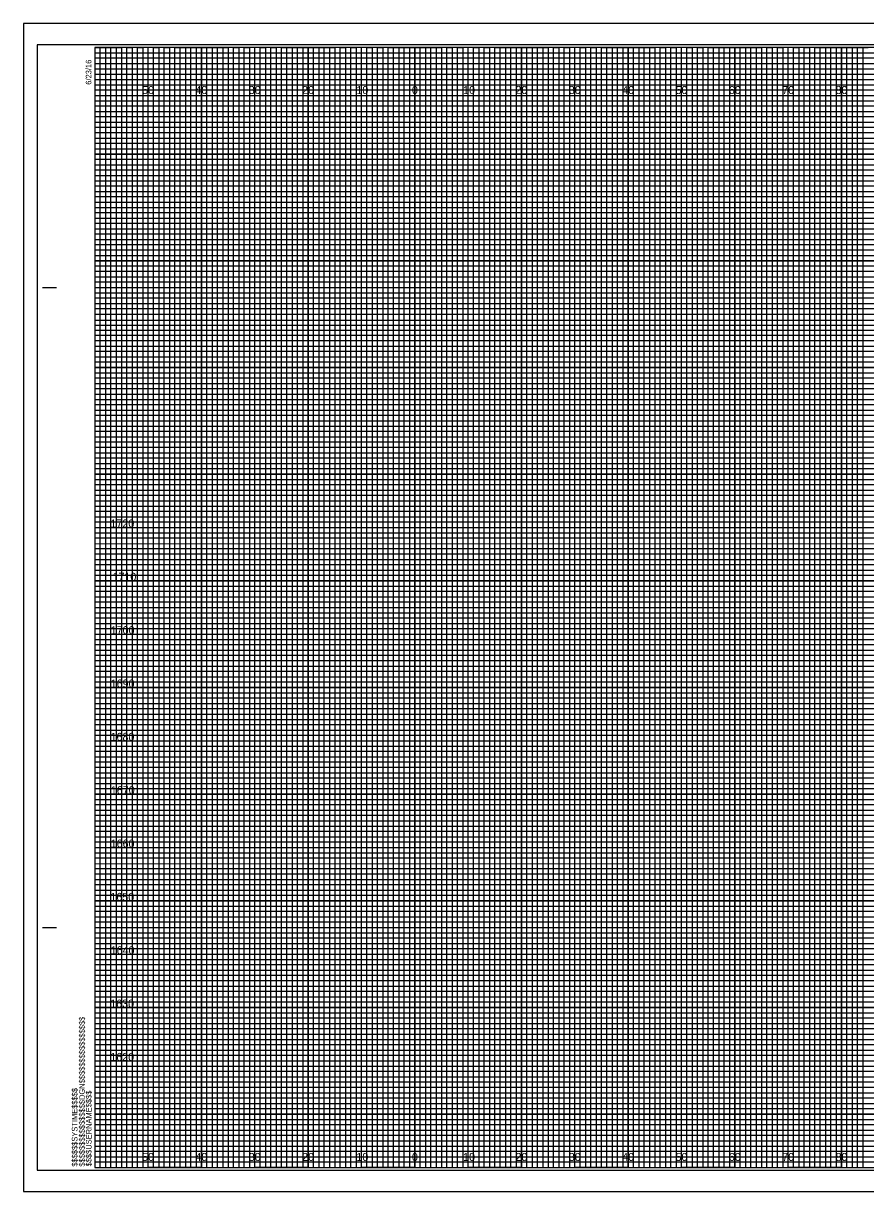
# Model space of a CAD drawing. Extents: x -13 to 323, y -5 to 6154.
# Drawn here: x -13.4 to 144.5, y 3295.5 to 3514.5 of the extents above; entities that cross this region are included whole.
import ezdxf

# ---------------------------------------------------------------- set-up
doc = ezdxf.new("R2010")
doc.units = 0
for name, color, linetype in [('Prop Retaining Wall', 7, 'Continuous'), ('Prop XS Alignment Label', 7, 'Continuous'), ('Prop XS DDE', 7, 'Continuous'), ('Prop XS DDE Elevations', 7, 'Continuous'), ('Prop XS DDE Slope Text', 7, 'Continuous'), ('Prop XS Earthwork Shape', 7, 'Continuous'), ('Prop XS Elevation Labels', 7, 'Continuous'), ('Prop XS Station Labels', 7, 'Continuous'), ('Raster_Level_0', 7, 'Continuous'), ('Scratch_Level_3', 7, 'Continuous'), ('Sheet Cutting Line CELL', 7, 'Continuous')]:
    doc.layers.add(name, color=color, linetype=linetype)

msp = doc.modelspace()

# ---------------------------------------------------------------- linework, layer by layer
at = {"layer": 'Prop Retaining Wall'}
for p, q in [((0, 3509), (260, 3509)), ((260, 3507.98), (0, 3507.98)), ((0, 3507.98), (0, 3507)), ((0, 3507), (260, 3507)), ((260, 3505.89), (0, 3505.89)), ((0, 3505.89), (0, 3504)), ((0, 3504), (320, 3504))]:
    msp.add_line(p, q, dxfattribs=at)
for points in [[(0, 3503), (270, 3503), (320, 3503), (320, 3502), (0, 3502)], [(0, 3501), (320, 3501), (320, 3499), (0, 3499)], [(0, 3498), (320, 3498), (320, 3497), (0, 3496.98)], [(0, 3496), (320, 3496), (320, 3494), (0, 3494)], [(0, 3493), (320, 3493), (320, 3492), (0, 3492)], [(0, 3491), (320, 3491), (320, 3489), (0, 3489)], [(0, 3488), (320, 3488), (320, 3487), (0, 3487)], [(0, 3486), (320, 3486), (320, 3484), (0, 3484)], [(0, 3483), (320, 3483), (320, 3482), (0, 3482)], [(0, 3481), (320, 3481), (320, 3479), (0, 3479)], [(0, 3478), (320, 3478), (320, 3477), (0, 3477)], [(0, 3476), (320, 3476), (320, 3473.95), (320, 3473), (320, 3472), (0, 3472)], [(0, 3474), (320, 3474), (320, 3473), (0, 3473)], [(0, 3471), (320, 3471), (320, 3469), (0, 3469.03)], [(0, 3469.03), (320, 3469), (320, 3468), (0, 3468)], [(0, 3467), (320, 3467), (320, 3466), (0, 3466)], [(0, 3464), (320, 3464), (320, 3463), (0, 3463)], [(0, 3462), (320, 3462), (320, 3461), (0, 3461)], [(-0.07, 3458.89), (320, 3458.89), (320, 3457.88), (-0.07, 3457.88)], [(0, 3457), (320, 3457), (320, 3456), (0, 3456)], [(0, 3454), (320, 3454), (320, 3453), (0, 3453)], [(0, 3452), (320, 3452), (320, 3451), (0, 3451)], [(0, 3449), (320, 3449), (320, 3448), (0, 3448)], [(0, 3447), (320, 3447), (320, 3446), (0, 3446)], [(0, 3444), (320, 3444), (320, 3443), (0, 3443)], [(0, 3442), (320, 3442), (320, 3441), (0, 3441)], [(0, 3439), (320, 3439), (319.99, 3437.98), (0, 3438)], [(0, 3437), (320, 3437), (320, 3436), (0, 3436)], [(0, 3434), (320, 3434), (320, 3433), (0, 3433)], [(0, 3432), (320, 3432), (320, 3431), (0, 3431)], [(0, 3429), (320, 3429), (320, 3428), (0, 3428)], [(0, 3427), (320, 3427), (320, 3426), (0, 3426)], [(0, 3424), (320, 3424), (320, 3423), (0, 3423)], [(0, 3422), (320, 3422), (320, 3421), (0, 3421)], [(0, 3419), (320, 3419), (320, 3418), (0, 3418)], [(0, 3416.99), (320.07, 3416.91), (320, 3416), (0, 3416)], [(0, 3414), (320, 3414), (320, 3413), (0, 3413)], [(0, 3412), (320, 3412), (320, 3411), (0, 3411)], [(0, 3409), (320, 3409), (320, 3408), (0, 3408)], [(0, 3407), (320, 3407), (320, 3406), (0, 3406)], [(0, 3404), (320, 3404), (320, 3403), (0, 3403)], [(0, 3402), (320, 3402), (320, 3401), (0, 3401)], [(0, 3399), (320, 3399), (320, 3398), (0, 3398)], [(0, 3397), (320, 3397), (320, 3396), (0, 3396)], [(0, 3394), (320, 3394), (320, 3393), (0, 3393)], [(0, 3392), (320, 3392), (320, 3391), (0, 3391)], [(0, 3389), (320, 3389), (320, 3388), (0, 3388)], [(0, 3387), (320, 3387), (320, 3386), (0, 3386)], [(0, 3384), (320, 3384), (320, 3383), (0, 3383)], [(0, 3382), (320, 3382), (320, 3381), (0, 3381)], [(0, 3379), (320, 3379), (319.99, 3377.98), (0, 3378)], [(0, 3377), (320, 3377), (320, 3376), (0, 3376)], [(0, 3374), (320, 3374), (320, 3373), (0, 3373)], [(0, 3372), (320, 3372), (320, 3371), (0, 3371)], [(0, 3369), (320, 3369), (320, 3368), (0, 3368)], [(0, 3367), (320, 3367), (320, 3366), (0, 3366)], [(0, 3364), (320, 3364), (320, 3363), (0, 3363)], [(0, 3362), (320, 3362), (320, 3361), (0, 3361)], [(0, 3359), (320, 3359), (320, 3358), (0, 3358)], [(0, 3356.99), (320.07, 3356.91), (320, 3356), (0, 3356)], [(0, 3354), (320, 3354), (320, 3353), (0, 3353)], [(0, 3352), (320, 3352), (320, 3351), (0, 3351)], [(0, 3349), (320, 3349), (320, 3348), (0, 3348)], [(0, 3347), (320, 3347), (320, 3346), (0, 3346)], [(0, 3344), (320, 3344), (320, 3343), (0, 3343)], [(0, 3342), (320, 3342), (320, 3341), (0, 3341)], [(0, 3339), (320, 3339), (320, 3338), (0, 3338)], [(0, 3337), (320, 3337), (320, 3336), (0, 3336)], [(0, 3334), (320, 3334), (320, 3333), (0, 3333)], [(0, 3332), (320, 3332), (320, 3331), (0, 3331)], [(0, 3329), (320, 3329), (320, 3328), (0, 3328)], [(0, 3327), (320, 3327), (320, 3326), (0, 3326)], [(0, 3324), (320, 3324), (320, 3323), (0, 3323)], [(0, 3322), (320, 3322), (320, 3321), (0, 3321)], [(0, 3319), (320, 3319), (320, 3318), (0, 3318)], [(0, 3317), (320, 3317), (320, 3316), (0, 3316)], [(0, 3314), (320, 3314), (320, 3313), (0, 3313)], [(0, 3312), (320, 3312), (320, 3311), (0, 3311)], [(0, 3309), (320, 3309), (320, 3308), (0, 3308)], [(0, 3307), (320, 3307), (320, 3306), (0, 3306)], [(0, 3304), (320, 3304), (320, 3303), (0, 3303)], [(0, 3302), (320, 3302), (320, 3301), (0, 3301)]]:
    msp.add_lwpolyline(points, dxfattribs=at)
at = {"layer": 'Prop XS Alignment Label'}
for p, q in [((-9.8, 3465), (-7.3, 3465)), ((-9.7, 3465), (-7.2, 3465)), ((-9.8, 3345), (-7.3, 3345)), ((-9.7, 3345), (-7.2, 3345)), ((0, 3300), (0, 3300)), ((0, 3300), (0, 3300)), ((0, 3300), (0, 3300)), ((0, 3300), (0, 3300)), ((0, 3300), (0, 3300)), ((0, 3300), (0, 3300)), ((0, 3300), (0, 3300))]:
    msp.add_line(p, q, dxfattribs=at)
msp.add_lwpolyline([(320, 3510), (0, 3510), (0, 3300), (320, 3300)], close=True, dxfattribs=at)
at = {"layer": 'Prop XS DDE'}
msp.add_lwpolyline([(-13.4, 3295.5), (323.3, 3295.5), (323.3, 3514.5), (-13.4, 3514.5)], close=True, dxfattribs=at)
at = {"layer": 'Prop XS DDE Elevations'}
for p, q in [((10, 3300), (10, 3510)), ((20, 3300), (20, 3510)), ((30, 3300), (30, 3510)), ((40, 3300), (40, 3510)), ((50, 3300), (50, 3510)), ((60, 3300), (60, 3510)), ((70, 3300), (70, 3510)), ((80, 3300), (80, 3510)), ((90, 3300), (90, 3510)), ((100, 3300), (100, 3510)), ((110, 3300), (110, 3510)), ((120, 3300), (120, 3510)), ((130, 3300), (130, 3510)), ((140, 3300), (140, 3510)), ((0, 3500), (320, 3500)), ((0, 3490), (320, 3490)), ((0, 3480), (320, 3480)), ((0, 3470), (320, 3470)), ((0, 3460), (320, 3460)), ((0, 3450), (320, 3450)), ((0, 3440), (320, 3440)), ((0, 3430), (320, 3430)), ((0, 3420), (320, 3420)), ((0, 3410), (320, 3410)), ((0, 3400), (320, 3400)), ((0, 3390), (320, 3390)), ((0, 3380), (320, 3380)), ((0, 3370), (320, 3370)), ((0, 3360), (320, 3360)), ((0, 3350), (320, 3350)), ((0, 3340), (320, 3340)), ((0, 3330), (320, 3330)), ((0, 3320), (320, 3320)), ((0, 3310), (320, 3310))]:
    msp.add_line(p, q, dxfattribs=at)
at = {"layer": 'Prop XS DDE Slope Text'}
msp.add_lwpolyline([(-10.8, 3299.5), (322.4, 3299.5), (322.4, 3510.5), (-10.8, 3510.5)], close=True, dxfattribs=at)
at = {"layer": 'Prop XS Earthwork Shape'}
for p, q in [((10, 3510), (0, 3510)), ((10, 3300), (10, 3510)), ((30, 3510), (20, 3510)), ((20, 3510), (20, 3300)), ((30, 3300), (30, 3510)), ((50, 3510), (40, 3510)), ((40, 3510), (40, 3300)), ((50, 3300), (50, 3510)), ((70, 3510), (60, 3510)), ((60, 3510), (60, 3300)), ((70, 3300), (70, 3510)), ((90, 3510), (80, 3510)), ((80, 3510), (80, 3300)), ((90, 3300), (90, 3510)), ((110, 3510), (100, 3510)), ((100, 3510), (100, 3300)), ((110, 3300), (110, 3510)), ((130, 3510), (120, 3510)), ((120, 3510), (120, 3300)), ((130, 3300), (130, 3510)), ((150, 3510), (140, 3510)), ((140, 3510), (140, 3300)), ((20, 3300), (10, 3300)), ((40, 3300), (30, 3300)), ((60, 3300), (50, 3300)), ((80, 3300), (70, 3300)), ((100, 3300), (90, 3300)), ((120, 3300), (110, 3300)), ((140, 3300), (130, 3300))]:
    msp.add_line(p, q, dxfattribs=at)
for points in [[(0, 3500), (320, 3500), (320, 3490), (0, 3490)], [(0, 3480), (320, 3480), (320, 3470), (0, 3470)], [(0, 3460), (320, 3460), (320, 3450), (0, 3450)], [(0, 3440), (320, 3440), (320, 3430), (0, 3430)], [(0, 3420), (320, 3420), (320, 3410), (0, 3410)], [(0, 3400), (320, 3400), (320, 3390), (0, 3390)], [(0, 3380), (320, 3380), (320, 3370), (0, 3370)], [(0, 3360), (320, 3360), (320, 3350), (0, 3350)], [(0, 3340), (320, 3340), (320, 3330), (0, 3330)], [(0, 3320), (320, 3320), (320, 3310), (0, 3310)]]:
    msp.add_lwpolyline(points, dxfattribs=at)
at = {"layer": 'Prop XS Elevation Labels'}
for points in [[(0, 3300), (1, 3300), (1, 3510), (2, 3510), (2, 3300)], [(2, 3300), (3, 3300), (3, 3510), (4, 3510), (4, 3300)], [(5, 3300), (6, 3300), (6, 3510), (7, 3510), (7, 3300)], [(7, 3300), (8, 3300), (8, 3510), (9, 3510), (9, 3300)], [(10, 3300), (11, 3300), (11, 3510), (12, 3510), (12, 3300)], [(12, 3300), (13, 3300), (13, 3510), (14, 3510), (14, 3300)], [(15, 3300), (16, 3300), (16, 3510), (17, 3510), (17, 3300)], [(17, 3300), (18, 3300), (18, 3510), (19, 3510), (19, 3300)], [(20, 3300), (21, 3300), (21, 3510), (22, 3510), (22, 3300)], [(22, 3300), (23, 3300), (23, 3510), (24, 3510), (24, 3300)], [(25, 3300), (26, 3300), (26, 3510), (27, 3510), (27, 3300)], [(27, 3300), (28, 3300), (28, 3510), (29, 3510), (29, 3300)], [(30, 3300), (31, 3300), (31, 3510), (32, 3510), (32, 3300)], [(32, 3300), (33, 3300), (33, 3510), (34, 3510), (34, 3300)], [(35, 3300), (36, 3300), (36, 3510), (37, 3510), (37, 3300)], [(37, 3300), (38, 3300), (38, 3510), (39, 3510), (39, 3300)], [(40, 3300), (41, 3300), (41, 3510), (42, 3510), (42, 3300)], [(42, 3300), (43, 3300), (43, 3510), (44, 3510), (44, 3300)], [(45, 3300), (46, 3300), (46, 3510), (47, 3510), (47, 3300)], [(47, 3300), (48, 3300), (48, 3510), (49, 3510), (49, 3300)], [(50, 3300), (51, 3300), (51, 3510), (52, 3510), (52, 3300)], [(52, 3300), (53, 3300), (53, 3510), (54, 3510), (54, 3300)], [(55, 3300), (56, 3300), (56, 3510), (57, 3510), (57, 3300)], [(57, 3300), (58, 3300), (58, 3510), (59, 3510), (59, 3300)], [(60, 3300), (61, 3300), (61, 3510), (62, 3510), (62, 3300)], [(62, 3300), (63, 3300), (63, 3510), (64, 3510), (64, 3300)], [(65, 3300), (66, 3300), (66, 3510), (67, 3510), (67, 3300)], [(67, 3300), (68, 3300), (68, 3510), (69, 3510), (69, 3300)], [(70, 3300), (71, 3300), (71, 3510), (72, 3510), (72, 3300)], [(72, 3300), (73, 3300), (73, 3510), (74, 3510), (74, 3300)], [(75, 3300), (76, 3300), (76, 3510), (77, 3510), (77, 3300)], [(77, 3300), (78, 3300), (78, 3510), (79, 3510), (79, 3300)], [(80, 3300), (81, 3300), (81, 3510), (82, 3510), (82, 3300)], [(82, 3300), (83, 3300), (83, 3510), (84, 3510), (84, 3300)], [(85, 3300), (86, 3300), (86, 3510), (87, 3510), (87, 3300)], [(87, 3300), (88, 3300), (88, 3510), (89, 3510), (89, 3300)], [(90, 3300), (91, 3300), (91, 3510), (92, 3510), (92, 3300)], [(92, 3300), (93, 3300), (93, 3510), (94, 3510), (94, 3300)], [(95, 3300), (96, 3300), (96, 3510), (97, 3510), (97, 3300)], [(97, 3300), (98, 3300), (98, 3510), (99, 3510), (99, 3300)], [(100, 3300), (101, 3300), (101, 3510), (102, 3510), (102, 3300)], [(102, 3300), (103, 3300), (103, 3510), (104, 3510), (104, 3300)], [(105, 3300), (106, 3300), (106, 3510), (107, 3510), (107, 3300)], [(107, 3300), (108, 3300), (108, 3510), (109, 3510), (109, 3300)], [(110, 3300), (111, 3300), (111, 3510), (112, 3510), (112, 3300)], [(112, 3300), (113, 3300), (113, 3510), (114, 3510), (114, 3300)], [(115, 3300), (116, 3300), (116, 3510), (117, 3510), (117, 3300)], [(117, 3300), (118, 3300), (118, 3510), (119, 3510), (119, 3300)], [(120, 3300), (121, 3300), (121, 3510), (122, 3510), (122, 3300)], [(122, 3300), (123, 3300), (123, 3510), (124, 3510), (124, 3300)], [(125, 3300), (126, 3300), (126, 3510), (127, 3510), (127, 3300)], [(127, 3300), (128, 3300), (128, 3510), (129, 3510), (129, 3300)], [(130, 3300), (131, 3300), (131, 3510), (132, 3510), (132, 3300)], [(132, 3300), (133, 3300), (133, 3510), (134, 3510), (134, 3300)], [(135, 3300), (136, 3300), (136, 3510), (137, 3510), (137, 3300)], [(137, 3300), (138, 3300), (138, 3510), (139, 3510), (139, 3300)], [(140, 3300), (141, 3300), (141, 3510), (142, 3510), (142, 3300)], [(142, 3300), (143, 3300), (143, 3510), (144, 3510), (144, 3300)]]:
    msp.add_lwpolyline(points, dxfattribs=at)
at = {"layer": 'Prop XS Station Labels'}
for points in [[(0, 3510), (5, 3510), (5, 3300), (15, 3300), (15, 3510), (25, 3510), (25, 3300), (35, 3300), (35, 3510), (45, 3510), (45, 3300), (55, 3300), (55, 3510), (65, 3510), (65, 3300), (75, 3300), (75, 3510), (85, 3510), (85, 3300), (95, 3300), (95, 3510), (105, 3510), (105, 3300), (115, 3300), (115, 3510), (125, 3510), (125, 3300), (135, 3300), (135, 3510), (145, 3510)], [(0, 3505), (275, 3505)], [(0, 3485), (320, 3485), (320, 3495), (0, 3495)], [(0, 3465), (320, 3465), (320, 3475), (0, 3475)], [(0, 3445), (320, 3445), (320, 3455), (0, 3455)], [(0, 3425), (320, 3425), (320, 3435), (0, 3435)], [(0, 3405), (320, 3405), (320, 3415), (0, 3415)], [(0, 3385), (320, 3385), (320, 3395), (0, 3395)], [(0, 3365), (320, 3365), (320, 3375), (0, 3375)], [(0, 3345), (320, 3345), (320, 3355), (0, 3355)], [(0, 3325), (320, 3325), (320, 3335), (0, 3335)], [(0, 3305), (320, 3305), (320, 3315), (0, 3315)]]:
    msp.add_lwpolyline(points, dxfattribs=at)
at = {"layer": 'Sheet Cutting Line CELL'}
for p, q in [((323.3, 3514.5), (-13.4, 3514.5)), ((-13.4, 3514.5), (-13.4, 3295.5)), ((-13.4, 3295.5), (323.3, 3295.5))]:
    msp.add_line(p, q, dxfattribs=at)

# ---------------------------------------------------------------- texts
at = {"layer": 'Prop XS Alignment Label'}
for s, p in [('6/23/16', (-0.65, 3503)), ('$$$$$$$$$$$$$$$$DGN$$$$$$$$$$$$$$$$', (-1.88, 3300.18)), ('$$$$$$SYSTIME$$$$$', (-3.26, 3300.18)), ('$$$$USERNAME$$$$', (-0.62, 3300.23))]:
    msp.add_text(s, height=1.05, rotation=90, dxfattribs=at).set_placement(p)
at = {"layer": 'Raster_Level_0'}
for s, p in [('50', (8.86, 3501.25)), ('40', (18.86, 3501.25)), ('30', (28.86, 3501.25)), ('20', (38.86, 3501.25)), ('10', (49.04, 3501.25)), ('0', (59.45, 3501.25)), ('0', (59.45, 3501.25)), ('10', (69.04, 3501.25)), ('20', (78.86, 3501.25)), ('30', (88.86, 3501.25)), ('40', (98.86, 3501.25)), ('50', (108.86, 3501.25)), ('60', (118.86, 3501.25)), ('70', (128.86, 3501.25)), ('80', (138.86, 3501.25)), ('50', (8.86, 3301.25)), ('40', (18.86, 3301.25)), ('30', (28.86, 3301.25)), ('20', (38.86, 3301.25)), ('10', (49.04, 3301.25)), ('0', (59.45, 3301.25)), ('0', (59.45, 3301.25)), ('10', (69.04, 3301.25)), ('20', (78.86, 3301.25)), ('30', (88.86, 3301.25)), ('40', (98.86, 3301.25)), ('50', (108.86, 3301.25)), ('60', (118.86, 3301.25)), ('70', (128.86, 3301.25)), ('80', (138.86, 3301.25))]:
    msp.add_text(s, height=1.5, dxfattribs=at).set_placement(p)
at = {"layer": 'Scratch_Level_3'}
for s, p in [('1720', (2.93, 3420)), ('1710', (3.31, 3410)), ('1700', (2.98, 3400)), ('1690', (2.97, 3390)), ('1680', (2.95, 3380)), ('1670', (3, 3370)), ('1660', (2.97, 3360)), ('1650', (2.92, 3350)), ('1640', (2.97, 3340)), ('1630', (2.89, 3330)), ('1620', (2.9, 3320))]:
    msp.add_text(s, height=1.5, dxfattribs=at).set_placement(p)

doc.saveas('drawing.dxf')
